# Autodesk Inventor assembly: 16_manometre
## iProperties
Created: 2002-11
Part Number: 16_manometre
Document SubType Name: Assemblage
Designer: FIEVET
Control State: 0
Master: False
Checked Out: False
Shininess: 41.0
Length Units: 11269
Angle Units: 11279
Time Units: 11290
Mass Units: 11283
Length Display Precision: 3
Angle Display Precision: 2
Compacted: True
Density: 0.0
Volumn: 0.0
Area: 0.0
PropertySet Name: Model Information
Author: FIEVET
